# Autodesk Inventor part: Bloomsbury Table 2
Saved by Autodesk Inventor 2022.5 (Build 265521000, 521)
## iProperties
Created: 2024-09
Part Number: Bloomsbury Table 2
Material: Generic
Document SubType Name: Modeling
Designer: AdminForWorker
Density: 1 g/cm^3
Appearance: Default
Title: Bloomsbury Table 2 v3
Author: AdminForWorker
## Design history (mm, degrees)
feature "Body1"
feature "Body2"
feature "Body3"
feature "Body4"
feature "Body7"
feature "Body11"
body "Solid1"
body "Solid2"
body "Solid3"
body "Solid4"
body "Solid5"
body "Solid6"
